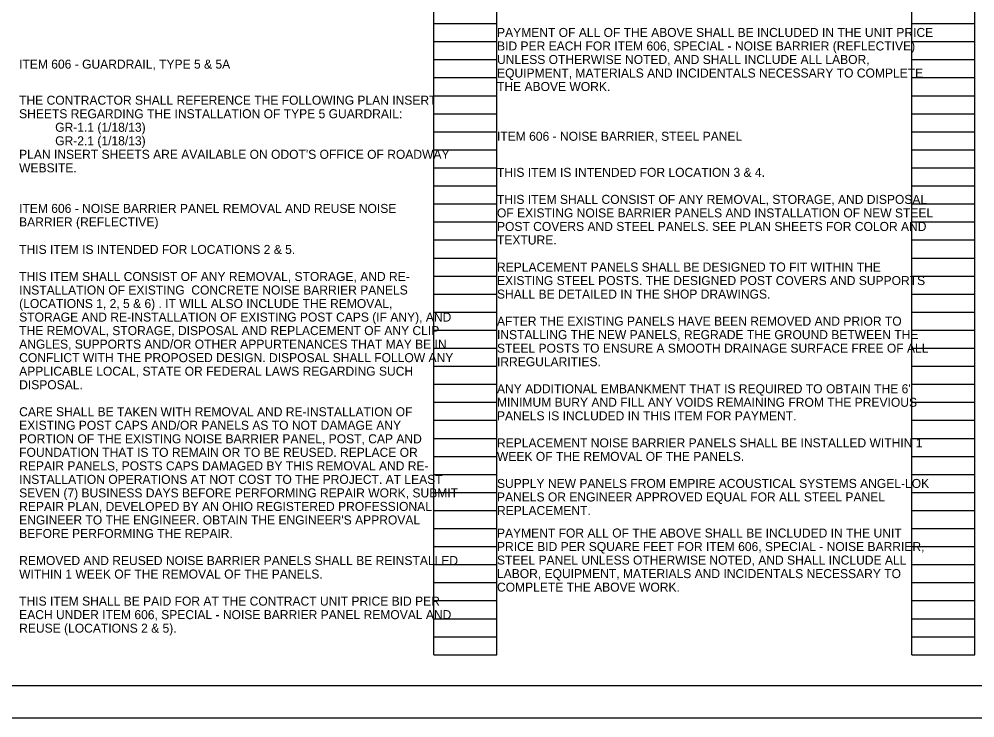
# Model space of a CAD drawing. Extents: x -10.6 to 34, y -3 to 22.
# Drawn here: x 9.82 to 24.66, y 0 to 10.85 of the extents above; entities that cross this region are included whole.
import ezdxf

# ---------------------------------------------------------------- set-up
doc = ezdxf.new("R2010")
doc.units = 0
for name, color, linetype in [('SH_Border', 7, 'Continuous'), ('SH_Cut_Line', 7, 'Continuous'), ('SH_Data', 7, 'Continuous'), ('SH_Text', 7, 'Continuous')]:
    doc.layers.add(name, color=color, linetype=linetype)

msp = doc.modelspace()

# ---------------------------------------------------------------- linework, layer by layer
at = {"layer": 'SH_Border'}
msp.add_lwpolyline([(1.5, 21.5), (33.5, 21.5), (33.5, 0.5), (1.5, 0.5)], close=True, dxfattribs=at)
at = {"layer": 'SH_Cut_Line'}
msp.add_lwpolyline([(0, 0), (34, 0), (34, 22), (0, 22)], close=True, dxfattribs=at)
at = {"layer": 'SH_Data'}
for p, q in [((16.26, 0.98), (16.26, 21.14)), ((17.24, 0.98), (17.24, 21.14)), ((23.68, 0.98), (23.68, 21.14)), ((24.66, 0.98), (24.66, 21.14)), ((16.26, 10.78), (17.24, 10.78)), ((23.68, 10.78), (24.66, 10.78)), ((16.26, 10.5), (17.24, 10.5)), ((23.68, 10.5), (24.66, 10.5)), ((16.26, 10.22), (17.24, 10.22)), ((23.68, 10.22), (24.66, 10.22)), ((16.26, 9.94), (17.24, 9.94)), ((23.68, 9.94), (24.66, 9.94)), ((16.26, 9.66), (17.24, 9.66)), ((23.68, 9.66), (24.66, 9.66)), ((16.26, 9.38), (17.24, 9.38)), ((23.68, 9.38), (24.66, 9.38)), ((16.26, 9.1), (17.24, 9.1)), ((23.68, 9.1), (24.66, 9.1)), ((16.26, 8.82), (17.24, 8.82)), ((23.68, 8.82), (24.66, 8.82)), ((16.26, 8.54), (17.24, 8.54)), ((23.68, 8.54), (24.66, 8.54)), ((16.26, 8.26), (17.24, 8.26)), ((23.68, 8.26), (24.66, 8.26)), ((16.26, 7.98), (17.24, 7.98)), ((23.68, 7.98), (24.66, 7.98)), ((16.26, 7.7), (17.24, 7.7)), ((23.68, 7.7), (24.66, 7.7)), ((16.26, 7.42), (17.24, 7.42)), ((23.68, 7.42), (24.66, 7.42)), ((16.26, 7.14), (17.24, 7.14)), ((23.68, 7.14), (24.66, 7.14)), ((16.26, 6.86), (17.24, 6.86)), ((23.68, 6.86), (24.66, 6.86)), ((16.26, 6.58), (17.24, 6.58)), ((23.68, 6.58), (24.66, 6.58)), ((16.26, 6.3), (17.24, 6.3)), ((23.68, 6.3), (24.66, 6.3)), ((16.26, 6.02), (17.24, 6.02)), ((23.68, 6.02), (24.66, 6.02)), ((16.26, 5.74), (17.24, 5.74)), ((23.68, 5.74), (24.66, 5.74)), ((16.26, 5.46), (17.24, 5.46)), ((23.68, 5.46), (24.66, 5.46)), ((16.26, 5.18), (17.24, 5.18)), ((23.68, 5.18), (24.66, 5.18)), ((16.26, 4.9), (17.24, 4.9)), ((23.68, 4.9), (24.66, 4.9)), ((16.26, 4.62), (17.24, 4.62)), ((23.68, 4.62), (24.66, 4.62)), ((16.26, 4.34), (17.24, 4.34)), ((23.68, 4.34), (24.66, 4.34)), ((16.26, 4.06), (17.24, 4.06)), ((23.68, 4.06), (24.66, 4.06)), ((16.26, 3.78), (17.24, 3.78)), ((23.68, 3.78), (24.66, 3.78)), ((16.26, 3.5), (17.24, 3.5)), ((23.68, 3.5), (24.66, 3.5)), ((16.26, 3.22), (17.24, 3.22)), ((23.68, 3.22), (24.66, 3.22)), ((16.26, 2.94), (17.24, 2.94)), ((23.68, 2.94), (24.66, 2.94)), ((16.26, 2.66), (17.24, 2.66)), ((23.68, 2.66), (24.66, 2.66)), ((16.26, 2.38), (17.24, 2.38)), ((23.68, 2.38), (24.66, 2.38)), ((16.26, 2.1), (17.24, 2.1)), ((23.68, 2.1), (24.66, 2.1)), ((16.26, 1.82), (17.24, 1.82)), ((23.68, 1.82), (24.66, 1.82)), ((16.26, 1.54), (17.24, 1.54)), ((23.68, 1.54), (24.66, 1.54)), ((16.26, 1.26), (17.24, 1.26)), ((23.68, 1.26), (24.66, 1.26)), ((16.26, 0.98), (17.24, 0.98)), ((23.68, 0.98), (24.66, 0.98))]:
    msp.add_line(p, q, dxfattribs=at)

# ---------------------------------------------------------------- texts
at = {"layer": 'SH_Text'}
for s, p in [('PAYMENT OF ALL OF THE ABOVE SHALL BE INCLUDED IN THE UNIT PRICE ', (17.241, 10.572)), ('BID PER EACH FOR ITEM 606, SPECIAL - NOISE BARRIER (REFLECTIVE) ', (17.241, 10.362)), ('UNLESS OTHERWISE NOTED, AND SHALL INCLUDE ALL LABOR, ', (17.241, 10.152)), ('ITEM 606 - GUARDRAIL, TYPE 5 & 5A', (9.82, 10.08)), ('EQUIPMENT, MATERIALS AND INCIDENTALS NECESSARY TO COMPLETE ', (17.241, 9.942)), ('THE ABOVE WORK.', (17.241, 9.732)), ('THE CONTRACTOR SHALL REFERENCE THE FOLLOWING PLAN INSERT ', (9.82, 9.52)), ('SHEETS REGARDING THE INSTALLATION OF TYPE 5 GUARDRAIL:', (9.82, 9.31)), ('GR-1.1 (1/18/13)', (10.38, 9.1)), ('ITEM 606 - NOISE BARRIER, STEEL PANEL', (17.24, 8.96)), ('GR-2.1 (1/18/13)', (10.38, 8.89)), ("PLAN INSERT SHEETS ARE AVAILABLE ON ODOT'S OFFICE OF ROADWAY ", (9.82, 8.68)), ('WEBSITE.', (9.82, 8.47)), ('THIS ITEM IS INTENDED FOR LOCATION 3 & 4.', (17.24, 8.4)), ('THIS ITEM SHALL CONSIST OF ANY REMOVAL, STORAGE, AND DISPOSAL ', (17.24, 7.98)), ('ITEM 606 - NOISE BARRIER PANEL REMOVAL AND REUSE NOISE ', (9.82, 7.84)), ('OF EXISTING NOISE BARRIER PANELS AND INSTALLATION OF NEW STEEL ', (17.24, 7.77)), ('BARRIER (REFLECTIVE)', (9.82, 7.63)), ('POST COVERS AND STEEL PANELS. SEE PLAN SHEETS FOR COLOR AND ', (17.24, 7.56)), ('TEXTURE.', (17.24, 7.35)), ('THIS ITEM IS INTENDED FOR LOCATIONS 2 & 5.', (9.821, 7.203)), ('REPLACEMENT PANELS SHALL BE DESIGNED TO FIT WITHIN THE ', (17.24, 6.93)), ('THIS ITEM SHALL CONSIST OF ANY REMOVAL, STORAGE, AND RE-', (9.821, 6.783)), ('EXISTING STEEL POSTS. THE DESIGNED POST COVERS AND SUPPORTS ', (17.24, 6.72)), ('INSTALLATION OF EXISTING  CONCRETE NOISE BARRIER PANELS ', (9.821, 6.573)), ('SHALL BE DETAILED IN THE SHOP DRAWINGS.', (17.24, 6.51)), ('(LOCATIONS 1, 2, 5 & 6) . IT WILL ALSO INCLUDE THE REMOVAL, ', (9.821, 6.363)), ('STORAGE AND RE-INSTALLATION OF EXISTING POST CAPS (IF ANY), AND ', (9.821, 6.153)), ('THE REMOVAL, STORAGE, DISPOSAL AND REPLACEMENT OF ANY CLIP ', (9.821, 5.943)), ('AFTER THE EXISTING PANELS HAVE BEEN REMOVED AND PRIOR TO ', (17.24, 6.09)), ('INSTALLING THE NEW PANELS, REGRADE THE GROUND BETWEEN THE ', (17.24, 5.88)), ('ANGLES, SUPPORTS AND/OR OTHER APPURTENANCES THAT MAY BE IN ', (9.821, 5.733)), ('STEEL POSTS TO ENSURE A SMOOTH DRAINAGE SURFACE FREE OF ALL ', (17.24, 5.67)), ('CONFLICT WITH THE PROPOSED DESIGN. DISPOSAL SHALL FOLLOW ANY ', (9.821, 5.523)), ('IRREGULARITIES.', (17.24, 5.46)), ('APPLICABLE LOCAL, STATE OR FEDERAL LAWS REGARDING SUCH ', (9.821, 5.313)), ('DISPOSAL.', (9.821, 5.103)), ('ANY ADDITIONAL EMBANKMENT THAT IS REQUIRED TO OBTAIN THE 6" ', (17.24, 5.04)), ('MINIMUM BURY AND FILL ANY VOIDS REMAINING FROM THE PREVIOUS ', (17.24, 4.83)), ('CARE SHALL BE TAKEN WITH REMOVAL AND RE-INSTALLATION OF ', (9.821, 4.683)), ('PANELS IS INCLUDED IN THIS ITEM FOR PAYMENT.', (17.24, 4.62)), ('EXISTING POST CAPS AND/OR PANELS AS TO NOT DAMAGE ANY ', (9.821, 4.473)), ('PORTION OF THE EXISTING NOISE BARRIER PANEL, POST, CAP AND ', (9.821, 4.263)), ('REPLACEMENT NOISE BARRIER PANELS SHALL BE INSTALLED WITHIN 1 ', (17.24, 4.2)), ('FOUNDATION THAT IS TO REMAIN OR TO BE REUSED. REPLACE OR ', (9.821, 4.053)), ('WEEK OF THE REMOVAL OF THE PANELS.', (17.24, 3.99)), ('REPAIR PANELS, POSTS CAPS DAMAGED BY THIS REMOVAL AND RE-', (9.821, 3.843)), ('INSTALLATION OPERATIONS AT NOT COST TO THE PROJECT. AT LEAST ', (9.821, 3.633)), ('SUPPLY NEW PANELS FROM EMPIRE ACOUSTICAL SYSTEMS ANGEL-LOK ', (17.24, 3.57)), ('SEVEN (7) BUSINESS DAYS BEFORE PERFORMING REPAIR WORK, SUBMIT ', (9.821, 3.423)), ('PANELS OR ENGINEER APPROVED EQUAL FOR ALL STEEL PANEL ', (17.24, 3.36)), ('REPAIR PLAN, DEVELOPED BY AN OHIO REGISTERED PROFESSIONAL ', (9.821, 3.213)), ('REPLACEMENT.', (17.24, 3.15)), ("ENGINEER TO THE ENGINEER. OBTAIN THE ENGINEER'S APPROVAL ", (9.821, 3.003)), ('BEFORE PERFORMING THE REPAIR. ', (9.821, 2.793)), ('PAYMENT FOR ALL OF THE ABOVE SHALL BE INCLUDED IN THE UNIT ', (17.24, 2.8)), ('PRICE BID PER SQUARE FEET FOR ITEM 606, SPECIAL - NOISE BARRIER, ', (17.24, 2.59)), ('REMOVED AND REUSED NOISE BARRIER PANELS SHALL BE REINSTALLED ', (9.821, 2.373)), ('STEEL PANEL UNLESS OTHERWISE NOTED, AND SHALL INCLUDE ALL ', (17.24, 2.38)), ('WITHIN 1 WEEK OF THE REMOVAL OF THE PANELS.', (9.821, 2.163)), ('LABOR, EQUIPMENT, MATERIALS AND INCIDENTALS NECESSARY TO ', (17.24, 2.17)), ('COMPLETE THE ABOVE WORK.', (17.24, 1.96)), ('THIS ITEM SHALL BE PAID FOR AT THE CONTRACT UNIT PRICE BID PER ', (9.821, 1.743)), ('EACH UNDER ITEM 606, SPECIAL - NOISE BARRIER PANEL REMOVAL AND ', (9.821, 1.533)), ('REUSE (LOCATIONS 2 & 5).', (9.821, 1.323))]:
    msp.add_text(s, height=0.14, dxfattribs=at).set_placement(p)

doc.saveas('drawing.dxf')
